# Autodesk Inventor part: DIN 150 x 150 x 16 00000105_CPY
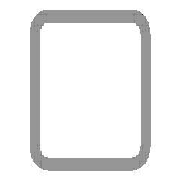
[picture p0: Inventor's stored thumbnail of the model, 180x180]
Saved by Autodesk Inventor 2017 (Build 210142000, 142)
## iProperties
Created: 2017-11
Part Number: DIN 150 x 150 x 16 00000105_CPY
Material: Steel, Mild
Description: Cold formed welded structural hollow sections of non-alloy and fine grain structural steel
Document SubType Name: Modeling
Standard: DIN
Designer: iusti
Standard Revision: 2006-07
Standards Organization: DIN
Language: en-US
Size Designation: 150 x 150 x 16
Categories: <MemberInstance><Categories><Category DisplayName="Structural Shapes" InternalName="089c4875-fa83-4c05-b084-43b9cc11f5ed" Mnemonic="GRDR"><CategoryParameter Dis
Stock Number: 150 x 150 x 16
Mass: 90369.3 g
Surface Area: 14539.6 cm^2
Volume: 11512 cm^3
Density: 7.85 g/cm^3
Appearance: Semi-Polished
IsCustomPart: 1
G_W: 150.000 mm
G_H: 150.000 mm
G_L: 1539.608 mm
+DD82D223-1000-45B8-A0F4-80F9EFDCC45E+CUTDETAIL2: Cut
_CCFamilyMember: 76
_CCFamilyDisplayName: DIN EN 10219-2 (Square Hollow Section - Cold Formed) - Cold formed welded structural hollow sections of non-alloy and fine grain structural steel
_FrameMemberDoc: Frame Member File
_Version: 15.0.0
_GetPNFromCC: 1
Author: iusti
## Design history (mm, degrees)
node "Start plane"
node "End plane"
sketch "Sketch"
  geometry: L1 (-75, -27)-(-75, 27); L2 (-27, 75)-(27, 75); L3 (75, 27)-(75, -27); L4 (27, -75)-(-27, -75); L5 (-27, 59)-(27, 59); L6 (59, 27)-(59, -27); L7 (27, -59)-(-27, -59); L8 (-59, -27)-(-59, 27); L9 (0, 118.918)-(0, -118.918) reference; L10 (-118.918, 0)-(118.918, 0) reference; A1 r 48 centre (-27, -27) between (-75, -27) and (-27, -75); A2 r 48 centre (-27, 27) between (-27, 75) and (-75, 27); A3 r 48 centre (27, 27) between (75, 27) and (27, 75); A4 r 48 centre (27, -27) between (27, -75) and (75, -27); A5 r 32 centre (-27, 27) between (-27, 59) and (-59, 27); A6 r 32 centre (27, 27) between (59, 27) and (27, 59); A7 r 32 centre (27, -27) between (27, -59) and (59, -27); A8 r 32 centre (-27, -27) between (-59, -27) and (-27, -59)
  constraints: 16 end point, 16 point on circle, 8 centre point, 8 tangent, 4 parallel, 3 equal radius, 2 perpendicular, 7 other
  dimensions: "d7" = 48 radius of A1 (= G_IR); "d10" = 150 distance between parallel lines of L2 L4 (= G_H); "d11" = 150 distance between parallel lines of L1 L3 (= G_W); "d12" = 16 distance between parallel lines of L3 L6 (= G_T); "d15" = 75 distance between parallel lines of L2 L10 (= 0.5 x d10); "d16" = 75 distance between parallel lines of L9 L3 (= 0.5 x d11)
extrude "Body" new body sketch "Sketch" stored distance "d3" = 1539.60835 (= G_L); taper "d4" = 0 deg
node "Driven Length"
  sketch "Sketch3"
    geometry: L1 (0, 0)-(10, 0) reference
    constraints: 2 end point, 1 horizontal
  workplane "Work Plane3"
  sketch "Sketch4"
    geometry: L1 (-2, 75)-(12, 75) reference; L2 (-2, 1614.608)-(12, 1614.608) reference
    dimensions: "d18" = 1539.60835 distance between parallel lines of L1 L2 (derived)
workplane "Work Plane5"
split "Split2"
body "Solid1"
other parameters: "G_W" = 150 [user parameter; used in 1 equation term], "G_H" = 150 [user parameter; used in 1 equation term], "G_T" = 16 [user parameter; used in 1 equation term], "G_IR" = 48 [user parameter; used in 1 equation term], "G_L" = 1539.60835 (= d18) [user parameter; used in 1 equation term], "G_OFFSET_START" = -75 [user parameter; used in 1 equation term], "G_OFFSET_END" = 0 [user parameter; used in 1 equation term], "d13" = 75 (= -G_OFFSET_START), "d14" = 1614.60835 (= G_OFFSET_END + B_L), "B_L" = 1614.60835 [user parameter; used in 1 equation term], "d17" = 90 deg
